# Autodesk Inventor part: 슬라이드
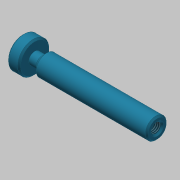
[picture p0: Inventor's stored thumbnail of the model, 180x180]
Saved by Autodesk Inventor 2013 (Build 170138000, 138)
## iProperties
Created: 2015-12
Part Number: 슬라이드
Document SubType Name: Modeling
Designer: mdu
Density: 8.08 g/cm^3
Material: 스테인리스강
Author: mdu
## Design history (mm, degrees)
sketch "스케치1"
  geometry: L1 (-45, 0)-(45, 0); L2 (-45, 0)-(-45, 10.5); L3 (-45, 10.5)-(-37, 10.5); L4 (-37, 10.5)-(-37, 4); L5 (-37, 4)-(-32, 4); L6 (-32, 4)-(-29, 7); L7 (-29, 7)-(45, 7); L8 (45, 7)-(45, 0); 2 further points
  constraints: 16 end point, 4 parallel, 2 perpendicular, 1 coincident, 1 horizontal, 1 midpoint
  dimensions: "d0" = 90 distance of L1.start L1.end; "d1" = 21 diameter of L3 L1; "d2" = 14 diameter of L7 L1; "d3" = 8 diameter of L5 L1; "d4" = 8 distance of L2.end L3.end; "d5" = 5 distance of L4.end L5.end; "d6" = 135 deg angle of L6 L5
revolve "회전1" sketch "스케치1" stored, may be unused: angle "d7" = 90 deg
chamfer "모따기1" distance "d8" = 1; stored, may be unused: second distance "d9" = 2, angle "d10" = 45 deg
hole "구멍1" diameter "d13" = 6.647; stored, may be unused: countersink angle "d17" = 90 deg, drill point angle "d19" = 118 deg; dims "d11" = 10, "d12" = 10, "d14" = 9, "d15" = 4, "d16" = 2, "d18" = 12
chamfer "모따기2" distance "d20" = 1; stored, may be unused: second distance "d21" = 2, angle "d22" = 45 deg
node "솔리드1"
